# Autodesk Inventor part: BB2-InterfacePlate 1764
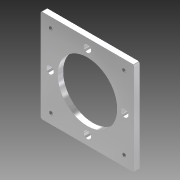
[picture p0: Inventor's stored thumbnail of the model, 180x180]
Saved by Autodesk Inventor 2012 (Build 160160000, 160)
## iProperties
Company: FirstCadLibrary
Shininess: 64.0
Length Units: 11269
Angle Units: 11279
Time Units: 11290
Mass Units: 11283
Length Display Precision: 3
Angle Display Precision: 2
Compacted: True
Part Number: BB2-InterfacePlate 1764
Document SubType Name: Modeling
Created: 2007-01
Material: Aluminum-6061
Designer: Ed Sparks
Catalog Web Link: www.banebots.com
Vendor: BaneBots
Mass: 26.5594 g
Surface Area: 70.4801 cm^2
Volume: 9.80051 cm^3
Density: 2.71 g/cm^3
Density: 0.0
Volumn: 0.0
Area: 0.0
PropertySet Name: Model Information
Control State: 0
Master: False
Checked Out: False
Author: Ed Sparks
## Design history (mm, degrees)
sketch "Sketch1"
  geometry: L1 (-31.75, 31.75)-(31.75, 31.75); L2 (31.75, 31.75)-(31.75, -31.75); L3 (31.75, -31.75)-(-31.75, -31.75); L4 (-31.75, -31.75)-(-31.75, 31.75); L5 (0, 0)-(31.75, 0); L6 (0, 0)-(-31.75, 0); L7 (0, 0)-(0, 31.75); L8 (0, 0)-(0, -31.75)
  constraints: 16 end point, 4 midpoint, 2 collinear, 2 parallel, 1 horizontal, 1 perpendicular, 1 other
  dimensions: "d0" = 63.5 distance of L1.start L1.end; "d1" = 63.5 distance of L1.end L2.end
extrude "Extrusion1" new body sketch "Sketch1" stored distance "d2" = 3.7; taper "d3" = 0 deg
sketch "Sketch2"
  geometry: 1 further point
hole "Hole1" sketch "Sketch2" at (0, 0) diameter "d4" = 40.45; stored, may be unused: countersink angle "d8" = 82 deg, drill point angle "d10" = 118 deg; dims "d5" = 6, "d6" = 4, "d7" = 2, "d9" = 8
sketch "Sketch3"
  geometry: C1 r 20.225 at (0, 0) reference; 1 further point
  constraints: 1 vertical alignment
  dimensions: "d11" = 25.4 distance of point (0, 25.4) C1.centre
hole "Hole2" sketch "Sketch3" at (0, 25.4) diameter "d12" = 5; stored, may be unused: countersink angle "d16" = 82 deg, drill point angle "d18" = 118 deg; dims "d13" = 6, "d14" = 4, "d15" = 2, "d17" = 8
pattern_circular "Circular Pattern1" dims angle "d21" = 360 deg
sketch "Sketch4"
  geometry: C1 r 2.5 at (-25.4, 0) reference; C2 r 2.5 at (0, 25.4) reference; 1 further point
  dimensions: "d24" = 24.82719 vertical distance of C1.centre point (-25, 24.827); "d25" = 25 horizontal distance of C2.centre point (-25, 24.827)
hole "Hole3" sketch "Sketch4" at (-25, 24.827) diameter "d26" = 2.459; stored, may be unused: countersink angle "d30" = 82 deg, drill point angle "d32" = 118 deg; dims "d27" = 6, "d28" = 4, "d29" = 2, "d31" = 8
pattern_circular "Circular Pattern2" dims angle "d35" = 360 deg
fillet "Fillet1" dims "d36" = 1
body "Solid1"
